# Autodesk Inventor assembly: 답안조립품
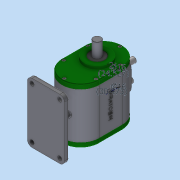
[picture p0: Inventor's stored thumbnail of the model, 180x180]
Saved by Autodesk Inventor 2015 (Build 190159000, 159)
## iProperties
Created: 2018-10
Part Number: 답안조립품
Document SubType Name: Assembly
Designer: SCD-A03
Author: SCD-A03
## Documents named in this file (15)
- C:\Users\SCD-A03\Desktop\381007V1058\답안조립품.iam
- C:\Users\SCD-A03\Desktop\381007V1058\본체.ipt
- C:\Users\SCD-A03\Desktop\381007V1058\뒤커버.ipt
- C:\Users\SCD-A03\Desktop\381007V1058\앞커버.ipt
- C:\Users\SCD-A03\Desktop\381007V1058\베어링 6003.ipt
- C:\Users\SCD-A03\Desktop\381007V1058\베어링 608.ipt
- C:\Users\SCD-A03\Desktop\381007V1058\오일실 17 32 8.ipt
- C:\Users\SCD-A03\Desktop\381007V1058\오일실 8 22 7.ipt
- C:\Users\SCD-A03\Desktop\381007V1058\부시.ipt
- C:\Users\SCD-A03\Desktop\381007V1058\슬라이더.ipt
- C:\Users\SCD-A03\Desktop\381007V1058\볼트 M4.ipt
- C:\Users\SCD-A03\Desktop\381007V1058\서브축.ipt
- C:\Users\SCD-A03\Desktop\381007V1058\메인축.ipt
- C:\Users\SCD-A03\Desktop\381007V1058\가변스프링1.ipt
- C:\Users\SCD-A03\Desktop\381007V1058\가변스프링2.ipt
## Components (2 placed, 2 different names)
1. 가변스프링1:1
2. 가변스프링2:1
